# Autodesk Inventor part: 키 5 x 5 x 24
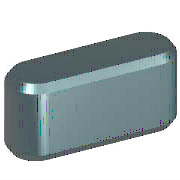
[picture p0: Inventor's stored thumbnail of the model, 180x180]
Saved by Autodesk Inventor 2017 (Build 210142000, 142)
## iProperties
IsCustomPart: 1
Created: 2012-02
Part Number: 키 5 x 5 x 24
Material: 강철, 연강
Description: 키 및 해당 키홈
Document SubType Name: Modeling
Standard: KS B 1311
Designer: mduedu
Standards Organization: KS
Language: ko-KR
Size Designation: 5 x 5 x 18
Categories: <MemberInstance><Categories><Category DisplayName="샤프트 부품" InternalName="7f7aeb1f-a693-4053-b835-cee3144e0d98" Mnemonic="SHFT"><Category DisplayName="키" Interna
Density: 1 g/cm^3
Appearance: 금색
Author: mduedu
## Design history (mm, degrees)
workplane "Work Plane1"
workplane "Work Plane2"
sketch "스케치1"
  geometry: L1 (2.5, 2.5)-(21.5, 2.5); L2 (21.5, -2.5)-(2.5, -2.5); L3 (0, 8.9)-(0, -4.4) reference; L4 (-3.6, 0)-(21.6, 0) reference; L5 (24, 0)-(24, 7); A1 r 2.5 centre (2.5, 0) between (2.5, 2.5) and (2.5, -2.5); A2 r 2.5 centre (21.5, 0) between (21.5, -2.5) and (21.5, 2.5)
  constraints: 6 end point, 5 point on circle, 4 tangent, 3 point on line, 2 centre point, 1 horizontal, 1 parallel, 1 perpendicular
  dimensions: "d0" = 2.5 radius of A1 (= 0.5 x PB); "d13" = 2.5 radius of A2 (= 0.5 x PB); "d14" = 24 distance between parallel lines of L5 L3 (= NLG)
extrude "본체1" new body sketch "스케치1" taper "d3" = 0 deg; stored distance "d4" = 10
workplane "Work Plane3"
body "Solid1"
chamfer "모따기1" distance "d8" = 0.4 (= PHH); stored, may be unused: second distance "d9" = 0.4 (= PHH), angle "d15" = 45 deg
other parameters: "d1" = -3 (= -PNT), "d2" = 2 (= PH - PNT), "NLG" = 24 [user parameter; used in 3 equation terms], "PB" = 5 [user parameter; used in 2 equation terms], "PNT" = 3 [user parameter; used in 2 equation terms], "PH" = 5 [user parameter; used in 1 equation term], "PHH" = 0.4 [user parameter; used in 2 equation terms], "d10" = 0, "d16" = 0, "d17" = 0, "d18" = 0, "WDMIN" = 12 [user parameter], "PLB2" = 24 (= NLG) [user parameter], "WDMAX" = 17 [user parameter], "PLB1" = 24 (= NLG) [user parameter], "RR" = 0.16 [user parameter], "PUEB" = 2.3 [user parameter]
